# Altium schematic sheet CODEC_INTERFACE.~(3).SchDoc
size A; SheetNumber: 2; SheetTotal: 2
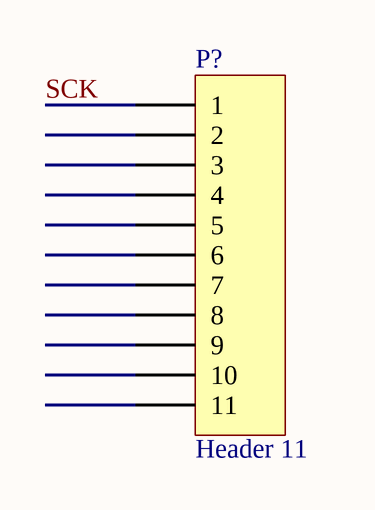
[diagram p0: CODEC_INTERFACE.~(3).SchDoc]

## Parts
P?  Header 11  [HDR1X11]

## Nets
SCK: P?.1

Not connected (* = marked no-connect by the designer): P? 2 3 4 5 6 7 8 9 10 11

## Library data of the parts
P? = Header 11: Header, 11-Pin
